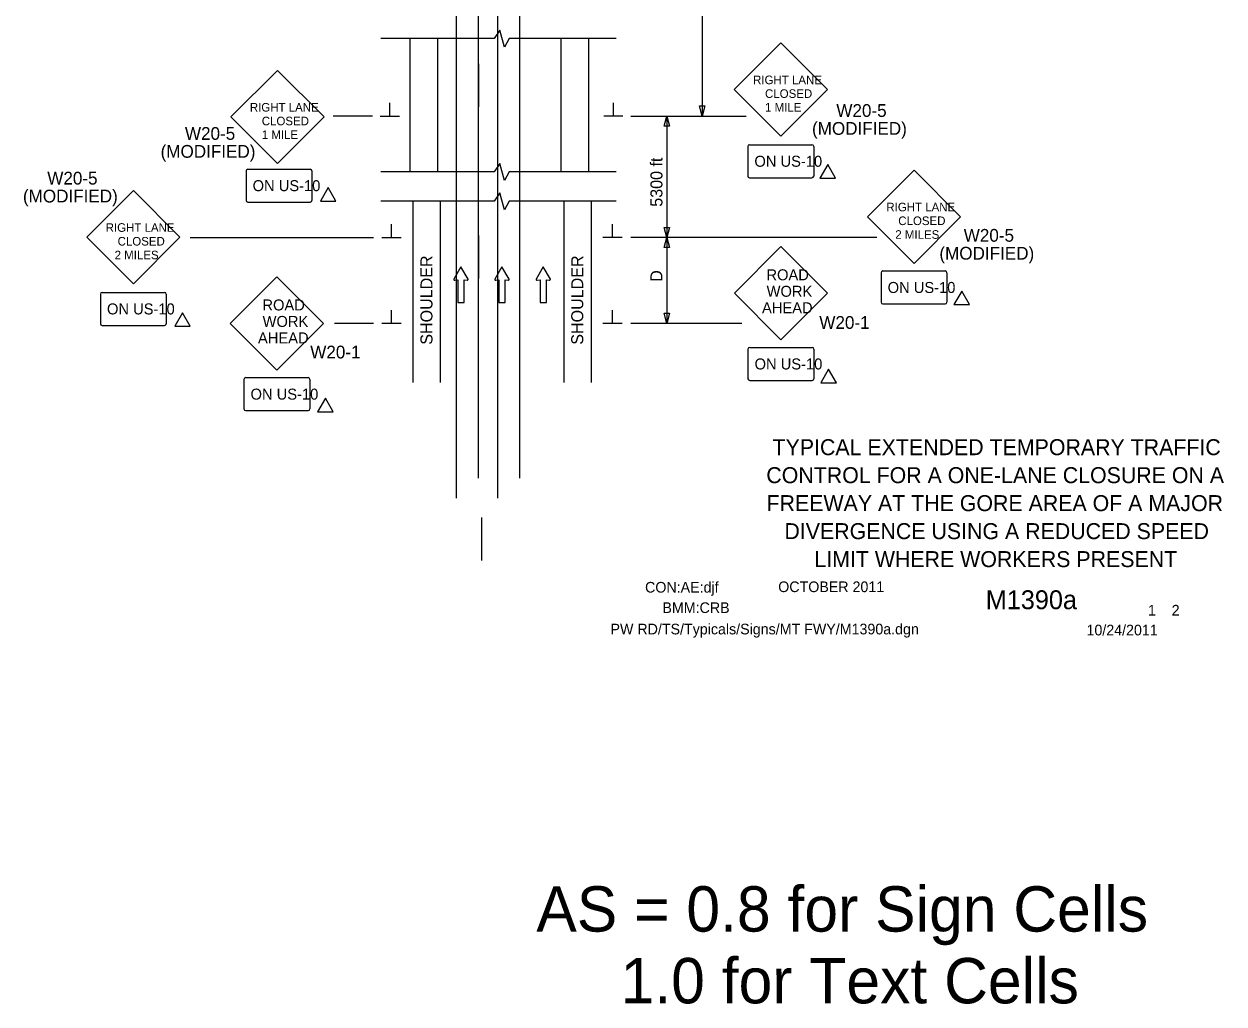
# Model space of a CAD drawing. Extents: x 16729 to 18475, y 5718 to 6974.
# Drawn here: x 16729 to 17428, y 5718 to 6289 of the extents above; entities that cross this region are included whole.
import ezdxf

# ---------------------------------------------------------------- set-up
doc = ezdxf.new("R2010")
doc.units = 0
for name, color, linetype in [('ALI_LEGAL_EX', 7, 'Continuous'), ('BORDER', 7, 'Continuous'), ('BORDER_SIGNAL_WO', 7, 'Continuous'), ('MT_SCRATCH_LEVEL_E', 7, 'Continuous'), ('PAVT_EDGE_EX', 7, 'Continuous'), ('TRAFFIC_SIGNS_PR', 7, 'Continuous'), ('TYPICAL_TEXT_DIMEN_PR', 7, 'Continuous')]:
    doc.layers.add(name, color=color, linetype=linetype)

msp = doc.modelspace()

# ---------------------------------------------------------------- linework, layer by layer
at = {"layer": 'ALI_LEGAL_EX'}
for p, q in [((16980.68, 6974.12), (16980.68, 6155.98)), ((17004.68, 6974.12), (17004.68, 6155.98)), ((16980.68, 6877.04), (16980.68, 6013.12)), ((17004.68, 6877.04), (17004.68, 6013.12)), ((16993.65, 6024.8), (16993.65, 6525.15)), ((17017.65, 6024.8), (17017.65, 6525.15))]:
    msp.add_line(p, q, dxfattribs=at)
for points in [[(16993.75, 6241.12), (16993.75, 6266.12)], [(17017.75, 6241.12), (17017.75, 6266.12)], [(16993.8, 6141.11), (16993.8, 6166.11)], [(17017.8, 6141.11), (17017.8, 6166.11)], [(16995.37, 6001.71), (16995.37, 5976.71)]]:
    msp.add_lwpolyline(points, dxfattribs=at)
at = {"layer": 'MT_SCRATCH_LEVEL_E'}
for p, q in [((16983.38, 6147.91), (16979.27, 6140.67)), ((16987.53, 6140.67), (16983.38, 6147.91)), ((17007.29, 6147.91), (17003.18, 6140.67)), ((17011.44, 6140.67), (17007.29, 6147.91)), ((17031.34, 6147.91), (17027.23, 6140.67)), ((17035.49, 6140.67), (17031.34, 6147.91)), ((16979.76, 6139.98), (16981.53, 6140.3)), ((16981.53, 6140.3), (16981.53, 6127.04)), ((16985.27, 6127.04), (16985.27, 6140.3)), ((16985.27, 6140.3), (16987.05, 6139.98)), ((17003.66, 6139.98), (17005.44, 6140.3)), ((17005.44, 6140.3), (17005.44, 6127.04)), ((17009.18, 6127.04), (17009.18, 6140.3)), ((17009.18, 6140.3), (17010.96, 6139.98)), ((17027.71, 6139.98), (17029.49, 6140.3)), ((17029.49, 6140.3), (17029.49, 6127.04)), ((17033.23, 6127.04), (17033.23, 6140.3)), ((17033.23, 6140.3), (17035.01, 6139.98)), ((16981.53, 6127.04), (16985.27, 6127.04)), ((17005.44, 6127.04), (17009.18, 6127.04)), ((17029.49, 6127.04), (17033.23, 6127.04))]:
    msp.add_line(p, q, dxfattribs=at)
for centre, start, end in [((16979.68, 6140.44), 150.42484, 279.96381), ((16987.12, 6140.44), 260.03619, 29.77312), ((17003.58, 6140.44), 150.42484, 279.96381), ((17011.03, 6140.44), 260.03619, 29.77312), ((17027.64, 6140.44), 150.42484, 279.96381), ((17035.08, 6140.44), 260.03619, 29.77312)]:
    msp.add_arc(centre, 0.463, start, end, dxfattribs=at)
at = {"layer": 'PAVT_EDGE_EX'}
for p, q in [((16953.65, 6280.88), (16953.65, 6203.23)), ((16969.65, 6280.88), (16969.65, 6203.23)), ((17041.65, 6280.88), (17041.65, 6203.23)), ((17057.65, 6280.88), (17057.65, 6203.23)), ((16955.37, 6186.1), (16955.37, 6080.42)), ((16971.37, 6186.1), (16971.37, 6080.42)), ((17043.37, 6186.1), (17043.37, 6080.42)), ((17059.37, 6186.1), (17059.37, 6080.42))]:
    msp.add_line(p, q, dxfattribs=at)
at = {"layer": 'TRAFFIC_SIGNS_PR'}
for p, q in [((17169.75, 6278.22), (17142.6, 6251.07)), ((17196.9, 6251.07), (17169.75, 6278.22)), ((16876.5, 6262.27), (16849.35, 6235.11)), ((16903.65, 6235.11), (16876.5, 6262.27)), ((17142.6, 6251.07), (17169.75, 6223.92)), ((17169.75, 6223.92), (17196.9, 6251.07)), ((16849.35, 6235.11), (16876.5, 6207.97)), ((16876.5, 6207.97), (16903.65, 6235.11)), ((17150.55, 6217.92), (17150.55, 6200.72)), ((17151.55, 6218.92), (17187.95, 6218.92)), ((17188.95, 6217.92), (17188.95, 6200.72)), ((16858.17, 6203.71), (16858.17, 6186.51)), ((16859.17, 6204.71), (16895.58, 6204.71)), ((16896.58, 6203.71), (16896.58, 6186.51)), ((17247.41, 6204.15), (17220.26, 6177)), ((17274.56, 6177), (17247.41, 6204.15)), ((17151.55, 6199.72), (17187.95, 6199.72)), ((16792.51, 6192.22), (16765.35, 6165.07)), ((16819.66, 6165.07), (16792.51, 6192.22)), ((16859.17, 6185.51), (16895.58, 6185.51)), ((17220.26, 6177), (17247.41, 6149.85)), ((17247.41, 6149.85), (17274.56, 6177)), ((16765.35, 6165.07), (16792.51, 6137.92)), ((16792.51, 6137.92), (16819.66, 6165.07)), ((17169.87, 6159.6), (17142.71, 6132.44)), ((17197.03, 6132.44), (17169.87, 6159.6)), ((16876.17, 6142.03), (16849.01, 6114.88)), ((16903.32, 6114.88), (16876.17, 6142.03)), ((17228.21, 6144.4), (17228.21, 6127.2)), ((17229.21, 6145.4), (17265.62, 6145.4)), ((17266.62, 6144.4), (17266.62, 6127.2)), ((16774.3, 6132.92), (16810.71, 6132.92)), ((16773.3, 6131.92), (16773.3, 6114.71)), ((16811.71, 6131.92), (16811.71, 6114.71)), ((17142.71, 6132.44), (17169.87, 6105.29)), ((17169.87, 6105.29), (17197.03, 6132.44)), ((17229.21, 6126.2), (17265.62, 6126.2)), ((16774.3, 6113.71), (16810.71, 6113.71)), ((16849.01, 6114.88), (16876.17, 6087.72)), ((16876.17, 6087.72), (16903.32, 6114.88)), ((17150.67, 6099.84), (17150.67, 6082.64)), ((17151.67, 6100.84), (17188.07, 6100.84)), ((17189.07, 6099.84), (17189.07, 6082.64)), ((16856.96, 6082.28), (16856.96, 6065.07)), ((16857.96, 6083.28), (16894.37, 6083.28)), ((16895.37, 6082.28), (16895.37, 6065.07)), ((17151.67, 6081.64), (17188.07, 6081.64)), ((16857.96, 6064.07), (16894.37, 6064.07))]:
    msp.add_line(p, q, dxfattribs=at)
for centre, start, end in [((17151.55, 6217.92), 90, 180), ((17187.95, 6217.92), 0, 90), ((16859.17, 6203.71), 90, 180), ((16895.58, 6203.71), 0, 90), ((17151.55, 6200.72), 180, 270), ((17187.95, 6200.72), 270, 0), ((16859.17, 6186.51), 180, 270), ((16895.58, 6186.51), 270, 0), ((17229.21, 6144.4), 90, 180), ((17265.62, 6144.4), 0, 90), ((16774.3, 6131.92), 90, 180), ((16810.71, 6131.92), 0, 90), ((17229.21, 6127.2), 180, 270), ((17265.62, 6127.2), 270, 0), ((16774.3, 6114.71), 180, 270), ((16810.71, 6114.71), 270, 0), ((17151.67, 6099.84), 90, 180), ((17188.07, 6099.84), 0, 90), ((16857.96, 6082.28), 90, 180), ((16894.37, 6082.28), 0, 90), ((17151.67, 6082.64), 180, 270), ((17188.07, 6082.64), 270, 0), ((16857.96, 6065.07), 180, 270), ((16894.37, 6065.07), 270, 0)]:
    msp.add_arc(centre, 1, start, end, dxfattribs=at)
at = {"layer": 'TYPICAL_TEXT_DIMEN_PR'}
for p, q in [((17124.01, 6619.33), (17124.01, 6235.65)), ((17002.72, 6280.88), (16936.78, 6280.88)), ((17005.97, 6285.68), (17002.72, 6280.88)), ((17008.71, 6275.74), (17005.97, 6285.68)), ((17011.46, 6280.88), (17008.71, 6275.74)), ((17073.79, 6280.88), (17011.46, 6280.88)), ((16941.96, 6235.65), (16941.96, 6243.44)), ((17072.21, 6235.65), (17072.21, 6243.44)), ((17124.01, 6235.65), (17122.44, 6241.52)), ((17122.44, 6241.52), (17124.01, 6241.52)), ((17124.01, 6241.52), (17125.58, 6241.52)), ((17125.58, 6241.52), (17124.01, 6235.65)), ((16931.8, 6235.65), (16908.94, 6235.65)), ((16936.33, 6235.65), (16947.58, 6235.65)), ((17077.83, 6235.65), (17066.58, 6235.65)), ((17082.37, 6235.65), (17149.63, 6235.65)), ((17101.8, 6229.79), (17103.37, 6235.65)), ((17103.37, 6235.65), (17103.37, 6164.88)), ((17103.37, 6235.65), (17104.94, 6229.79)), ((17103.37, 6229.79), (17101.8, 6229.79)), ((17104.94, 6229.79), (17103.37, 6229.79)), ((17002.72, 6203.23), (16936.78, 6203.23)), ((17005.97, 6208.03), (17002.72, 6203.23)), ((17008.71, 6198.1), (17005.97, 6208.03)), ((17011.46, 6203.23), (17008.71, 6198.1)), ((17073.79, 6203.23), (17011.46, 6203.23)), ((17005.97, 6190.9), (17002.72, 6186.1)), ((17008.71, 6180.96), (17005.97, 6190.9)), ((17002.72, 6186.1), (16936.78, 6186.1)), ((17011.46, 6186.1), (17008.71, 6180.96)), ((17073.79, 6186.1), (17011.46, 6186.1)), ((16942.99, 6164.88), (16942.99, 6172.66)), ((17071.74, 6164.88), (17071.74, 6172.66)), ((17103.37, 6164.88), (17101.8, 6170.74)), ((17101.8, 6170.74), (17103.37, 6170.74)), ((17103.37, 6170.74), (17104.94, 6170.74)), ((17104.94, 6170.74), (17103.37, 6164.88)), ((16825.62, 6164.88), (16932.37, 6164.88)), ((16937.37, 6164.88), (16948.62, 6164.88)), ((17077.37, 6164.88), (17066.12, 6164.88)), ((17225.72, 6164.88), (17082.37, 6164.88)), ((17101.8, 6159.01), (17103.37, 6164.88)), ((17103.37, 6164.88), (17103.37, 6114.88)), ((17103.37, 6164.88), (17104.94, 6159.01)), ((17103.37, 6159.01), (17101.8, 6159.01)), ((17104.94, 6159.01), (17103.37, 6159.01)), ((16942.99, 6114.88), (16942.99, 6122.66)), ((17071.74, 6114.88), (17071.74, 6122.66)), ((17103.37, 6114.88), (17101.8, 6120.74)), ((17101.8, 6120.74), (17103.37, 6120.74)), ((17103.37, 6120.74), (17104.94, 6120.74)), ((17104.94, 6120.74), (17103.37, 6114.88)), ((16932.37, 6114.88), (16909.74, 6114.88)), ((16948.62, 6114.88), (16937.37, 6114.88)), ((17077.37, 6114.88), (17066.12, 6114.88)), ((17146.99, 6114.88), (17082.37, 6114.88))]:
    msp.add_line(p, q, dxfattribs=at)
for points in [[(17197.1, 6207.36), (17192.58, 6199.53), (17201.63, 6199.53)], [(16906.06, 6194), (16901.53, 6186.16), (16910.59, 6186.16)], [(17275.21, 6133.66), (17270.69, 6125.82), (17279.74, 6125.82)], [(16821.11, 6121.05), (16816.58, 6113.22), (16825.64, 6113.22)], [(17197.67, 6088.14), (17193.14, 6080.31), (17202.2, 6080.31)], [(16904.42, 6071.28), (16899.89, 6063.44), (16908.95, 6063.44)]]:
    msp.add_lwpolyline(points, close=True, dxfattribs=at)

# ---------------------------------------------------------------- texts
at = {"layer": 'BORDER'}
for s, p in [('TYPICAL EXTENDED TEMPORARY TRAFFIC', (17164.97, 6038.11)), ('CONTROL FOR A ONE-LANE CLOSURE ON A', (17161.34, 6021.81)), ('FREEWAY AT THE GORE AREA OF A MAJOR', (17161.47, 6005.51)), (' DIVERGENCE USING A REDUCED SPEED', (17168.44, 5989.2)), ('LIMIT WHERE WORKERS PRESENT', (17189.34, 5972.9))]:
    msp.add_text(s, height=9.3, dxfattribs=at).set_placement(p)
at = {"layer": 'BORDER_SIGNAL_WO'}
for s, height, p in [('CON:AE:djf  ', 6.2, (17090.69, 5958.06)), ('    OCTOBER 2011    ', 6.2, (17159.08, 5958.34)), ('    M1390a   ', 11, (17272.86, 5948.38)), ('BMM:CRB   ', 6.2, (17100.81, 5946.17)), (' 1    2 ', 6.2, (17381.45, 5944.7)), ('PW RD/TS/Typicals/Signs/MT FWY/M1390a.dgn      ', 6.2, (17070.55, 5933.71)), ('10/24/2011    ', 6.2, (17347.93, 5933.13)), ('AS = 0.8 for Sign Cells', 26.4241, (17027.34, 5760.56)), ('     1.0 for Text Cells', 26.4241, (17027.34, 5718.77))]:
    msp.add_text(s, height=height, dxfattribs=at).set_placement(p)
at = {"layer": 'TRAFFIC_SIGNS_PR'}
for s, height, p in [('RIGHT LANE', 4.999, (17153.63, 6254.23)), ('CLOSED', 4.999, (17160.59, 6246.23)), ('RIGHT LANE', 4.999, (16860.39, 6238.27)), ('1 MILE', 4.999, (17160.58, 6238.23)), ('W20-5', 7.439, (17202.15, 6235.16)), ('CLOSED', 4.999, (16867.34, 6230.27)), ('(MODIFIED)', 7.439, (17187.97, 6224.72)), ('W20-5', 7.439, (16822.57, 6221.8)), ('1 MILE', 4.999, (16867.34, 6222.27)), ('(MODIFIED)', 7.439, (16808.39, 6211.36)), ('ON US-10', 6.401, (17154.39, 6206.12)), ('W20-5', 7.439, (16742.35, 6195.76)), ('ON US-10', 6.401, (16862.01, 6191.91)), ('(MODIFIED)', 7.439, (16728.17, 6185.32)), ('RIGHT LANE', 4.999, (17231.29, 6180.15)), ('CLOSED', 4.999, (17238.25, 6172.15)), ('RIGHT LANE', 4.999, (16776.39, 6168.22)), ('2 MILES', 4.999, (17236.5, 6164.15)), ('W20-5', 7.439, (17276.38, 6162.45)), ('CLOSED', 4.999, (16783.34, 6160.22)), ('2 MILES', 4.999, (16781.59, 6152.22)), ('(MODIFIED)', 7.439, (17262.2, 6152.02)), ('ROAD', 6.401, (17161.41, 6139.98)), ('WORK', 6.401, (17161.52, 6130.38)), ('ON US-10', 6.401, (17232.05, 6132.6)), ('ON US-10', 6.401, (16777.14, 6120.11)), ('ROAD', 6.401, (16867.71, 6122.41)), ('AHEAD', 6.401, (17158.83, 6120.78)), ('WORK', 6.401, (16867.82, 6112.81)), ('W20-1', 7.441, (17192.22, 6111.68)), ('AHEAD', 6.401, (16865.13, 6103.21)), ('W20-1', 7.441, (16895.58, 6094.46)), ('ON US-10', 6.401, (17154.51, 6088.04)), ('ON US-10', 6.401, (16860.8, 6070.47))]:
    msp.add_text(s, height=height, dxfattribs=at).set_placement(p)
at = {"layer": 'TYPICAL_TEXT_DIMEN_PR'}
for s, p in [('5300 ft', (17100.81, 6182.83)), ('SHOULDER', (16966.81, 6102.45)), ('SHOULDER', (17054.67, 6102.45)), ('D', (17100.81, 6139.1))]:
    msp.add_text(s, height=7, rotation=90, dxfattribs=at).set_placement(p)

doc.saveas('drawing.dxf')
